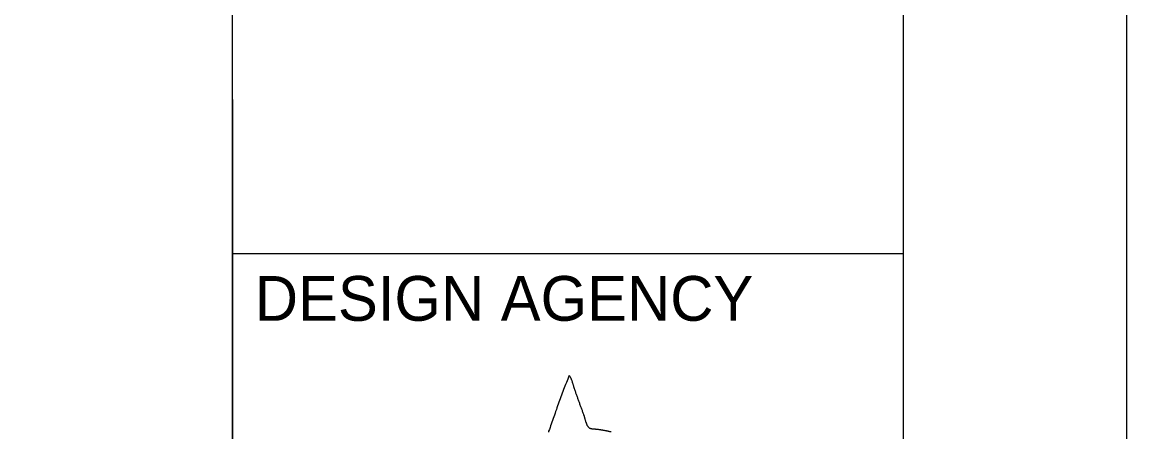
# Model space of a CAD drawing. Extents: x 0 to 1700, y 0 to 1100.
# Drawn here: x 1576.5 to 1700, y 205.1 to 250.8 of the extents above; entities that cross this region are included whole.
import ezdxf

# ---------------------------------------------------------------- set-up
doc = ezdxf.new("R2010")
doc.units = 0
for name, color, linetype in [('DT_X_Contour_Minor', 7, 'Continuous'), ('DT_X_Contour_Text', 7, 'Continuous'), ('DT_X_Terrain_Ground_Line', 7, 'Continuous'), ('DT_X_Triangles', 7, 'Continuous')]:
    doc.layers.add(name, color=color, linetype=linetype)

msp = doc.modelspace()

# ---------------------------------------------------------------- linework, layer by layer
at = {"layer": 'DT_X_Contour_Minor'}
for p, q in [((1600, 25), (1600, 1075)), ((1600, 225), (1675, 225))]:
    msp.add_line(p, q, dxfattribs=at)
msp.add_lwpolyline([(75, 1075), (1675, 1075), (1675, 25), (75, 25)], close=True, dxfattribs=at)
at = {"layer": 'DT_X_Contour_Text'}
msp.add_line((1600, 242.21), (1600, 25), dxfattribs=at)
for points in [[(1637.66, 211.38), (1637.58, 211.19), (1637.49, 211), (1637.41, 210.8), (1637.33, 210.6), (1637.25, 210.4), (1637.17, 210.21), (1637.09, 210.01), (1637.01, 209.81), (1636.93, 209.61), (1636.86, 209.41), (1636.78, 209.21), (1636.71, 209.01), (1636.64, 208.8), (1636.56, 208.6), (1636.49, 208.4), (1636.42, 208.19), (1636.35, 207.99), (1636.28, 207.79), (1636.21, 207.59), (1636.13, 207.39), (1636.07, 207.18), (1636, 206.98), (1635.92, 206.78), (1635.86, 206.58), (1635.78, 206.38), (1635.71, 206.18), (1635.64, 205.97), (1635.57, 205.77), (1635.5, 205.57), (1635.43, 205.37), (1635.35, 205.18)], [(1638.28, 209.8), (1638.26, 209.84), (1638.24, 209.89), (1638.23, 209.94), (1638.21, 209.99), (1638.2, 210.04), (1638.18, 210.1), (1638.17, 210.15), (1638.15, 210.21), (1638.13, 210.26), (1638.12, 210.32), (1638.1, 210.37), (1638.09, 210.43), (1638.07, 210.48), (1638.05, 210.53), (1638.03, 210.59), (1638.01, 210.64), (1638, 210.7), (1637.98, 210.75), (1637.96, 210.81), (1637.93, 210.86), (1637.92, 210.91), (1637.89, 210.97), (1637.87, 211.01), (1637.85, 211.07), (1637.83, 211.12), (1637.8, 211.17), (1637.78, 211.21), (1637.75, 211.26), (1637.72, 211.3), (1637.69, 211.34), (1637.66, 211.38)], [(1639.28, 207.02), (1639.25, 207.11), (1639.22, 207.2), (1639.18, 207.29), (1639.15, 207.38), (1639.12, 207.47), (1639.09, 207.56), (1639.05, 207.64), (1639.02, 207.73), (1638.98, 207.82), (1638.95, 207.91), (1638.92, 208), (1638.89, 208.09), (1638.85, 208.18), (1638.82, 208.27), (1638.79, 208.36), (1638.75, 208.45), (1638.72, 208.54), (1638.69, 208.63), (1638.66, 208.72), (1638.63, 208.81), (1638.6, 208.9), (1638.56, 208.98), (1638.53, 209.07), (1638.5, 209.16), (1638.47, 209.26), (1638.43, 209.35), (1638.4, 209.43), (1638.37, 209.52), (1638.34, 209.61), (1638.31, 209.7), (1638.28, 209.8)], [(1639.89, 205.53), (1639.86, 205.56), (1639.83, 205.59), (1639.8, 205.62), (1639.77, 205.65), (1639.75, 205.69), (1639.72, 205.73), (1639.69, 205.78), (1639.67, 205.82), (1639.64, 205.87), (1639.63, 205.93), (1639.6, 205.98), (1639.58, 206.03), (1639.57, 206.09), (1639.54, 206.14), (1639.52, 206.19), (1639.5, 206.25), (1639.49, 206.31), (1639.47, 206.37), (1639.46, 206.42), (1639.44, 206.48), (1639.43, 206.54), (1639.41, 206.59), (1639.4, 206.65), (1639.38, 206.7), (1639.37, 206.75), (1639.35, 206.8), (1639.34, 206.85), (1639.32, 206.9), (1639.31, 206.94), (1639.3, 206.98), (1639.28, 207.02)], [(1635.35, 205.18), (1635.33, 205.13), (1635.32, 205.08)], [(1640.69, 205.38), (1640.67, 205.38), (1640.64, 205.38), (1640.62, 205.38), (1640.6, 205.38), (1640.57, 205.39), (1640.54, 205.39), (1640.52, 205.39), (1640.49, 205.39), (1640.46, 205.39), (1640.43, 205.39), (1640.4, 205.39), (1640.38, 205.39), (1640.35, 205.4), (1640.32, 205.4), (1640.29, 205.41), (1640.26, 205.41), (1640.23, 205.41), (1640.21, 205.41), (1640.18, 205.42), (1640.15, 205.42), (1640.12, 205.43), (1640.1, 205.44), (1640.07, 205.44), (1640.04, 205.45), (1640.02, 205.46), (1640, 205.47), (1639.98, 205.48), (1639.95, 205.49), (1639.93, 205.5), (1639.91, 205.52), (1639.89, 205.53)], [(1642.18, 205.12), (1642.13, 205.13), (1642.09, 205.14), (1642.04, 205.15), (1641.99, 205.16), (1641.94, 205.17), (1641.89, 205.18), (1641.84, 205.19), (1641.8, 205.2), (1641.75, 205.21), (1641.71, 205.22), (1641.66, 205.22), (1641.61, 205.24), (1641.56, 205.24), (1641.51, 205.25), (1641.46, 205.26), (1641.41, 205.27), (1641.37, 205.28), (1641.32, 205.29), (1641.27, 205.3), (1641.22, 205.3), (1641.17, 205.31), (1641.12, 205.32), (1641.07, 205.33), (1641.03, 205.33), (1640.98, 205.34), (1640.93, 205.35), (1640.89, 205.35), (1640.84, 205.36), (1640.79, 205.36), (1640.74, 205.37), (1640.69, 205.38)], [(1642.33, 205.09), (1642.18, 205.12)]]:
    msp.add_lwpolyline(points, dxfattribs=at)
at = {"layer": 'DT_X_Terrain_Ground_Line'}
msp.add_lwpolyline([(0, 0), (1700, 0), (1700, 1100), (0, 1100)], close=True, dxfattribs=at)

# ---------------------------------------------------------------- texts
at = {"layer": 'DT_X_Triangles'}
msp.add_text('DESIGN AGENCY', height=5, dxfattribs=at).set_placement((1602.5, 217.5))

doc.saveas('drawing.dxf')
